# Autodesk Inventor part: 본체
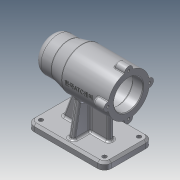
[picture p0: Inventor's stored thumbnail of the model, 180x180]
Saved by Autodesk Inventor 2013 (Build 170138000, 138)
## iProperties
Created: 2019-07
Part Number: 본체
Material: 알루미늄 6061
Document SubType Name: Modeling
Designer: user
Mass: 646.775 g
Surface Area: 654.094 cm^2
Volume: 238.662 cm^3
Density: 2.71 g/cm^3
Author: user
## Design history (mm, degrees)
sketch "스케치1"
  geometry: L1 (-56, 0)-(56, 0); L2 (56, 0)-(56, 30); L3 (56, 30)-(-11, 30); L4 (-11, 30)-(-31, 25); L5 (-31, 25)-(-56, 25); L6 (-56, 25)-(-56, 0); 2 further points
  constraints: 12 end point, 2 parallel, 2 perpendicular, 1 coincident, 1 horizontal, 1 midpoint
  dimensions: "d0" = 112 distance of L1.start L1.end; "d1" = 60 diameter of L3 L1; "d2" = 50 diameter of L5 L1; "d3" = 25 distance of L4.end L5.end; "d4" = 45 horizontal distance of L3.end L5.end
revolve "회전1" sketch "스케치1" stored, may be unused: angle "d5" = 90 deg
sketch "스케치2"
  geometry: L1 (-56, -25)-(-56, 25) reference; L2 (56, -30)-(56, 30) reference; L3 (-56, 0)-(56, 0); L4 (56, 0)-(56, 21); L5 (56, 21)-(41, 21); L6 (41, 21)-(41, 24); L7 (41, 24)-(-13, 24); L8 (-13, 24)-(-13, 21); L9 (-13, 21)-(-25, 21); L10 (-25, 21)-(-25, 17.5); L11 (-25, 17.5)-(-43, 17.5); L12 (-43, 17.5)-(-43, 16); L13 (-43, 16)-(-47, 16); L14 (-47, 16)-(-47, 10.5); L15 (-47, 10.5)-(-50, 10.5); L16 (-50, 10.5)-(-50, 0); 1 further point
  constraints: 28 end point, 8 parallel, 3 perpendicular, 2 midpoint, 2 point on line, 1 collinear
  dimensions: "d6" = 42 diameter of L5 L3; "d8" = 48 diameter of L7 L3; "d9" = 42 diameter of L9 L3; "d10" = 35 diameter of L11 L3; "d11" = 32 diameter of L13 L3; "d12" = 21 diameter of L15 L3; "d13" = 3 distance of L14.end L15.end; "d14" = 4 distance of L12.end L13.end; "d15" = 18 distance of L10.end L11.end; "d16" = 12 horizontal distance of L7.end L9.end; "d17" = 54 distance of L6.end L7.end; "d18" = 15 horizontal distance of L4.end L6.end
revolve "회전2" sketch "스케치2" stored, may be unused: angle "d19" = 90 deg
fillet "모깎기1" dims "d20" = 3
fillet "모깎기2" dims "d21" = 0.3
fillet "모깎기3" dims "d22" = 10
fillet "모깎기4" dims "d23" = 3
sketch "스케치3"
  geometry: L1 (0, 0)-(0, 30); C1 r 30 at (0, 0) reference; C2 r 6 at (0, 30)
  constraints: 2 end point, 1 centre point, 1 coincident, 1 vertical
  dimensions: "d24" = 30 distance of L1.start L1.end; "d25" = 12 diameter of C2
extrude "돌출1" join sketch "스케치3" distance "d26" = 16; taper "d27" = 0 deg
sketch "스케치4"
  geometry: A1 r 6 centre (0, 0) between (5.97, -0.6) and (-5.97, -0.6) reference; 1 further point
  constraints: 1 coincident
hole "구멍1" sketch "스케치4" at (0, 0) diameter "d28" = 3.242; stored, may be unused: countersink angle "d32" = 90 deg, drill point angle "d34" = 118 deg; dims "d29" = 8, "d30" = 4, "d31" = 2, "d33" = 11
node "작업 평면1"
sketch "스케치5"
  geometry: L1 (-56, 35)-(56, 35); L2 (56, 35)-(56, -35); L3 (56, -35)-(-56, -35); L4 (-56, -35)-(-56, 35); L5 (-56, 35)-(56, -35); L6 (56, 35)-(-56, -35); 1 further point
  constraints: 12 end point, 2 midpoint, 2 parallel, 1 horizontal, 1 perpendicular
  dimensions: "d40" = 112 distance of L2.end L3.end; "d41" = 70 distance of L1.end L2.end
extrude "돌출2" join sketch "스케치5" distance "d42" = 10; taper "d43" = 0 deg
sketch "스케치6"
  geometry: L1 (56, 35)-(-56, 35) reference; L2 (-56, 35)-(-56, -35) reference; L3 (-36, 4)-(31, 4); L4 (31, 4)-(31, -4); L5 (31, -4)-(-36, -4); L6 (-36, -4)-(-36, 4); 1 further point
  constraints: 8 end point, 2 parallel, 1 horizontal, 1 perpendicular
  dimensions: "d44" = 67 distance of L4.end L5.end; "d45" = 8 distance of L3.end L4.end; "d46" = 20 distance between parallel lines of L2 L6; "d47" = 31 distance between parallel lines of L3 L1
extrude "돌출3" join sketch "스케치6" stored distance "d48" = 10; taper "d49" = 0 deg
feature "면 기울기1" dims angle "d50" = 20 deg
sketch "스케치7"
  geometry: L1 (-80, 35)-(-70, 35) reference; L2 (-70, 35)-(-70, 4) reference; L3 (-70, 4)-(-29.732, 4) reference; L4 (-29.732, -4)-(-70, -4) reference; L5 (-70, -4)-(-70, -35) reference; L6 (-70, -35)-(-80, -35) reference; L7 (-80, -35)-(-80, 35) reference; L8 (-70, 28)-(-22.666, 19.654); C1 r 24 at (0, 0) reference; A1 r 30 centre (0, 0) between (-29.732, -4) and (-29.732, 4) reference; 1 further point
  constraints: 2 end point, 1 point on circle, 1 point on line
  dimensions: "d51" = 7 vertical distance of L8.start L1.start; "d52" = 100 deg angle of L8 L2
feature "리브1" sketch "스케치7" dims "d53" = 1, "d54" = 8, "d55" = 0, "d56" = 0, "d57" = 1, "d58" = 1
fillet "모깎기6" dims "d59" = 10
sketch "스케치8"
  geometry: A1 r 10 centre (-46, 25) between (-46, 35) and (-56, 25) reference; A2 r 10 centre (-46, -25) between (-56, -25) and (-46, -35) reference; A3 r 10 centre (46, -25) between (46, -35) and (56, -25) reference; A4 r 10 centre (46, 25) between (56, 25) and (46, 35) reference; 5 further points
  constraints: 4 coincident
hole "구멍2" sketch "스케치8" at (-46, 25), (46, 25), (46, -25), (-46, -25) diameter "d60" = 6; stored, may be unused: countersink angle "d64" = 90 deg, drill point angle "d66" = 118 deg; dims "d61" = 8, "d62" = 4, "d63" = 2, "d65" = 11
fillet "모깎기7" dims "d67" = 3
fillet "모깎기8" dims "d68" = 3
chamfer "모따기1" distance "d69" = 3; stored, may be unused: second distance "d70" = 2, angle "d71" = 45 deg
fillet "모깎기9" dims "d72" = 3
fillet "모깎기10" dims "d73" = 1
chamfer "모따기2" distance "d74" = 1; stored, may be unused: second distance "d75" = 2, angle "d76" = 45 deg
node "작업 평면2"
sketch "스케치9"
  geometry: L1 (33.5, 6.771)-(33.5, 29.226) reference; 2 further points
  constraints: 1 other
  dimensions: "d77" = 0 vertical distance of point (-22.5, 0) point (-8.5, 0); "d78" = 42 distance from line of L1 point (-8.5, 0)
feature "엠보싱1" sketch "스케치9" dims "d6" = 42, "d8" = 48, "d9" = 42, "d10" = 35, "d11" = 32, "d12" = 21, "d13" = 3, "d14" = 4, "d15" = 18, "d16" = 12, "d17" = 54, "d18" = 15, "d79" = 0.5, "d80" = 0
node "솔리드1"
pattern_circular "원형 패턴1" dims angle "d36" = 360 deg
mirror "대칭1"
node "절단 모서리 투영1"
